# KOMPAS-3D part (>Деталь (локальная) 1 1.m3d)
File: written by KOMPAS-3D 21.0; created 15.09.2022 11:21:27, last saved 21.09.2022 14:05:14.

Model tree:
1. Операция без истории:1
2. Развертка  (labels: Сталь 45  ГОСТ 1050-2013)

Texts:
  Толщина листового тела
  Глубина освобождения сгиба
  Ширина освобождения сгиба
